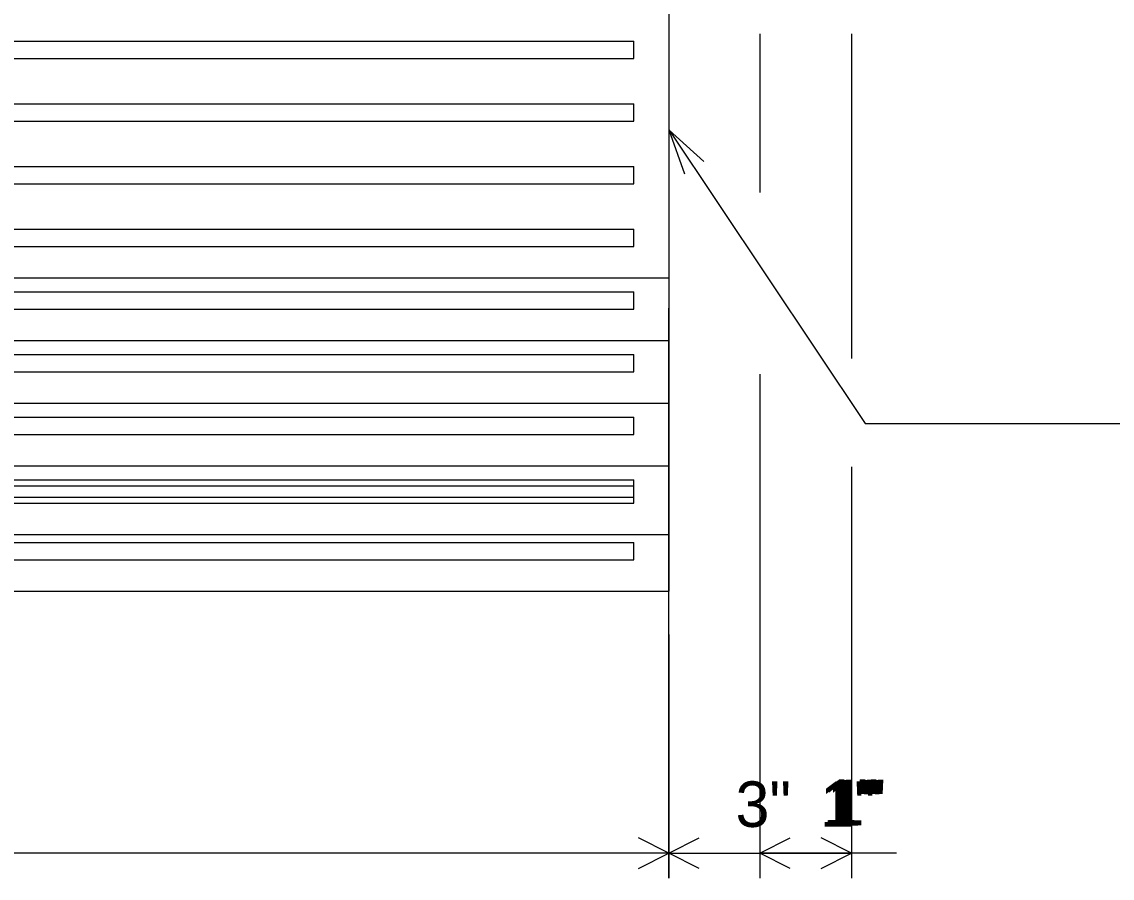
# Model space of a CAD drawing. Extents: x 997.7 to 1009.7, y 1494.3 to 1503.3.
# Drawn here: x 1001.614 to 1002.611, y 1499.262 to 1500.045 of the extents above; entities that cross this region are included whole.
import ezdxf

# ---------------------------------------------------------------- set-up
doc = ezdxf.new("R2010")
doc.units = 0
for name, color, linetype in [('Level 10', 7, 'Continuous'), ('Level 11', 7, 'Continuous'), ('Level 12', 7, 'Continuous'), ('Level 13', 7, 'Continuous'), ('Level 14', 7, 'Continuous'), ('Level 15', 7, 'Continuous'), ('Level 2', 7, 'Continuous'), ('Level 4', 7, 'Continuous'), ('Level 5', 7, 'Continuous'), ('Level 6', 7, 'Continuous'), ('Level 7', 7, 'Continuous'), ('Level 8', 7, 'Continuous'), ('Level 9', 7, 'Continuous')]:
    doc.layers.add(name, color=color, linetype=linetype)

msp = doc.modelspace()

# ---------------------------------------------------------------- linework, layer by layer
at = {"layer": 'Level 10'}
for p, q in [((1002.20583, 1499.92558), (1002.20583, 1499.75373)), ((1000.90445, 1499.79818), (1002.17378, 1499.79818)), ((1002.17378, 1499.78255), (1002.17378, 1499.79818)), ((1000.90445, 1499.78255), (1002.17378, 1499.78255)), ((1000.8725, 1499.75373), (1002.20583, 1499.75373)), ((1002.20583, 1499.26217), (1002.20583, 1499.72333))]:
    msp.add_line(p, q, dxfattribs=at)
at = {"layer": 'Level 11'}
for p, q in [((1002.20583, 1499.92558), (1002.20583, 1499.69644)), ((1000.90445, 1499.79818), (1002.17378, 1499.79818)), ((1002.17378, 1499.78255), (1002.17378, 1499.79818)), ((1000.90445, 1499.78255), (1002.17378, 1499.78255)), ((1000.90445, 1499.74088), (1002.17378, 1499.74088)), ((1002.17378, 1499.72526), (1002.17378, 1499.74088)), ((1000.90445, 1499.72526), (1002.17378, 1499.72526)), ((1000.8725, 1499.69644), (1002.20583, 1499.69644)), ((1002.20583, 1499.26217), (1002.20583, 1499.65907))]:
    msp.add_line(p, q, dxfattribs=at)
at = {"layer": 'Level 12'}
for p, q in [((1002.20583, 1499.92558), (1002.20583, 1499.63914)), ((1000.90445, 1499.79818), (1002.17378, 1499.79818)), ((1002.17378, 1499.78255), (1002.17378, 1499.79818)), ((1000.90445, 1499.78255), (1002.17378, 1499.78255)), ((1000.90445, 1499.74088), (1002.17378, 1499.74088)), ((1002.17378, 1499.72526), (1002.17378, 1499.74088)), ((1000.90445, 1499.72526), (1002.17378, 1499.72526)), ((1000.90445, 1499.68359), (1002.17378, 1499.68359)), ((1002.17378, 1499.66797), (1002.17378, 1499.68359)), ((1000.90445, 1499.66797), (1002.17378, 1499.66797)), ((1000.8725, 1499.63914), (1002.20583, 1499.63914)), ((1002.20583, 1499.26217), (1002.20583, 1499.60846))]:
    msp.add_line(p, q, dxfattribs=at)
at = {"layer": 'Level 13'}
for p, q in [((1002.20583, 1499.92558), (1002.20583, 1499.57637)), ((1000.90445, 1499.79818), (1002.17378, 1499.79818)), ((1002.17378, 1499.78255), (1002.17378, 1499.79818)), ((1000.90445, 1499.78255), (1002.17378, 1499.78255)), ((1000.90445, 1499.74088), (1002.17378, 1499.74088)), ((1002.17378, 1499.72526), (1002.17378, 1499.74088)), ((1000.90445, 1499.72526), (1002.17378, 1499.72526)), ((1000.90445, 1499.68359), (1002.17378, 1499.68359)), ((1002.17378, 1499.66797), (1002.17378, 1499.68359)), ((1000.90445, 1499.66797), (1002.17378, 1499.66797)), ((1000.90445, 1499.62082), (1002.17378, 1499.62082)), ((1002.17378, 1499.60519), (1002.17378, 1499.62082)), ((1000.90445, 1499.60519), (1002.17378, 1499.60519)), ((1000.8725, 1499.57637), (1002.20583, 1499.57637)), ((1002.20583, 1499.26217), (1002.20583, 1499.54125))]:
    msp.add_line(p, q, dxfattribs=at)
at = {"layer": 'Level 14'}
for p, q in [((1002.20583, 1499.92558), (1002.20583, 1499.52456)), ((1000.90445, 1499.79818), (1002.17378, 1499.79818)), ((1002.17378, 1499.78255), (1002.17378, 1499.79818)), ((1000.90445, 1499.78255), (1002.17378, 1499.78255)), ((1000.90445, 1499.74088), (1002.17378, 1499.74088)), ((1002.17378, 1499.72526), (1002.17378, 1499.74088)), ((1000.90445, 1499.72526), (1002.17378, 1499.72526)), ((1000.90445, 1499.68359), (1002.17378, 1499.68359)), ((1002.17378, 1499.66797), (1002.17378, 1499.68359)), ((1000.90445, 1499.66797), (1002.17378, 1499.66797)), ((1000.90445, 1499.6263), (1002.17378, 1499.6263)), ((1002.17378, 1499.61068), (1002.17378, 1499.6263)), ((1000.90445, 1499.61068), (1002.17378, 1499.61068)), ((1000.90445, 1499.56901), (1002.17378, 1499.56901)), ((1002.17378, 1499.55338), (1002.17378, 1499.56901)), ((1000.90445, 1499.55338), (1002.17378, 1499.55338)), ((1000.8725, 1499.52456), (1002.20583, 1499.52456)), ((1002.20583, 1499.48493), (1002.20583, 1499.26217))]:
    msp.add_line(p, q, dxfattribs=at)
at = {"layer": 'Level 15'}
for p, q in [((1002.37283, 1500.03415), (1002.37283, 1499.73743)), ((1002.37283, 1499.63839), (1002.37283, 1499.26217)), ((1002.20583, 1499.28508), (1002.37283, 1499.28508))]:
    msp.add_line(p, q, dxfattribs=at)
for points in [[(1002.23358, 1499.27117), (1002.20583, 1499.28508), (1002.23358, 1499.299)], [(1002.34508, 1499.27117), (1002.37283, 1499.28508), (1002.34508, 1499.299)]]:
    msp.add_lwpolyline(points, dxfattribs=at)
at = {"layer": 'Level 2'}
for p, q in [((1002.20583, 1500.05617), (1002.20583, 1499.92558)), ((1000.90445, 1500.02734), (1002.17378, 1500.02734)), ((1002.17378, 1500.01172), (1002.17378, 1500.02734)), ((1000.90445, 1500.01172), (1002.17378, 1500.01172)), ((1000.90445, 1499.97005), (1002.17378, 1499.97005)), ((1002.17378, 1499.95443), (1002.17378, 1499.97005)), ((1000.90445, 1499.95443), (1002.17378, 1499.95443)), ((1002.206, 1499.94617), (1002.38533, 1499.67775)), ((1000.90445, 1499.91276), (1002.17378, 1499.91276)), ((1002.17378, 1499.89713), (1002.17378, 1499.91276)), ((1000.90445, 1499.89713), (1002.17378, 1499.89713)), ((1000.90445, 1499.85547), (1002.17378, 1499.85547)), ((1002.17378, 1499.83984), (1002.17378, 1499.85547)), ((1000.90445, 1499.83984), (1002.17378, 1499.83984)), ((1002.38542, 1499.67783), (1002.64614, 1499.67783)), ((1002.20583, 1499.28508), (1000.8725, 1499.28508))]:
    msp.add_line(p, q, dxfattribs=at)
for points in [[(1002.2205, 1499.90575), (1002.206, 1499.94617), (1002.23783, 1499.91733)], [(1002.17808, 1499.27117), (1002.20583, 1499.28508), (1002.17808, 1499.299)]]:
    msp.add_lwpolyline(points, dxfattribs=at)
at = {"layer": 'Level 4'}
for p, q in [((1002.28917, 1500.03415), (1002.28917, 1499.889)), ((1002.28917, 1499.72308), (1002.28917, 1499.26217)), ((1002.41417, 1499.28508), (1002.28917, 1499.28508))]:
    msp.add_line(p, q, dxfattribs=at)
msp.add_lwpolyline([(1002.31692, 1499.27117), (1002.28917, 1499.28508), (1002.31692, 1499.299)], dxfattribs=at)
at = {"layer": 'Level 5'}
for p, q in [((1002.28917, 1500.03415), (1002.28917, 1499.889)), ((1002.28917, 1499.72308), (1002.28917, 1499.26217)), ((1002.41417, 1499.28508), (1002.28917, 1499.28508))]:
    msp.add_line(p, q, dxfattribs=at)
msp.add_lwpolyline([(1002.31692, 1499.27117), (1002.28917, 1499.28508), (1002.31692, 1499.299)], dxfattribs=at)
at = {"layer": 'Level 6'}
for p, q in [((1002.28917, 1500.03415), (1002.28917, 1499.889)), ((1002.28917, 1499.72308), (1002.28917, 1499.26217)), ((1002.41417, 1499.28508), (1002.28917, 1499.28508))]:
    msp.add_line(p, q, dxfattribs=at)
msp.add_lwpolyline([(1002.31692, 1499.27117), (1002.28917, 1499.28508), (1002.31692, 1499.299)], dxfattribs=at)
at = {"layer": 'Level 7'}
for p, q in [((1002.28917, 1500.03415), (1002.28917, 1499.889)), ((1002.28917, 1499.72308), (1002.28917, 1499.26217)), ((1002.41417, 1499.28508), (1002.28917, 1499.28508))]:
    msp.add_line(p, q, dxfattribs=at)
msp.add_lwpolyline([(1002.31692, 1499.27117), (1002.28917, 1499.28508), (1002.31692, 1499.299)], dxfattribs=at)
at = {"layer": 'Level 8'}
for p, q in [((1002.28917, 1500.03415), (1002.28917, 1499.889)), ((1002.28917, 1499.72308), (1002.28917, 1499.26217)), ((1002.41417, 1499.28508), (1002.28917, 1499.28508))]:
    msp.add_line(p, q, dxfattribs=at)
msp.add_lwpolyline([(1002.31692, 1499.27117), (1002.28917, 1499.28508), (1002.31692, 1499.299)], dxfattribs=at)
at = {"layer": 'Level 9'}
for p, q in [((1002.20583, 1499.92558), (1002.20583, 1499.81102)), ((1000.8725, 1499.81102), (1002.20583, 1499.81102)), ((1002.20583, 1499.26217), (1002.20583, 1499.78333))]:
    msp.add_line(p, q, dxfattribs=at)

# ---------------------------------------------------------------- texts
at = {"layer": 'Level 15'}
msp.add_text('3" ', height=0.041667, dxfattribs=at).set_placement((1002.26685, 1499.30901))
at = {"layer": 'Level 4'}
msp.add_text('1" ', height=0.041667, dxfattribs=at).set_placement((1002.35363, 1499.31052))
at = {"layer": 'Level 5'}
msp.add_text('1" ', height=0.041667, dxfattribs=at).set_placement((1002.34422, 1499.30914))
at = {"layer": 'Level 6'}
msp.add_text('1" ', height=0.041667, dxfattribs=at).set_placement((1002.3505, 1499.31022))
at = {"layer": 'Level 7'}
msp.add_text('1" ', height=0.041667, dxfattribs=at).set_placement((1002.34736, 1499.31087))
at = {"layer": 'Level 8'}
msp.add_text('1" ', height=0.041667, dxfattribs=at).set_placement((1002.34697, 1499.31047))

doc.saveas('drawing.dxf')
